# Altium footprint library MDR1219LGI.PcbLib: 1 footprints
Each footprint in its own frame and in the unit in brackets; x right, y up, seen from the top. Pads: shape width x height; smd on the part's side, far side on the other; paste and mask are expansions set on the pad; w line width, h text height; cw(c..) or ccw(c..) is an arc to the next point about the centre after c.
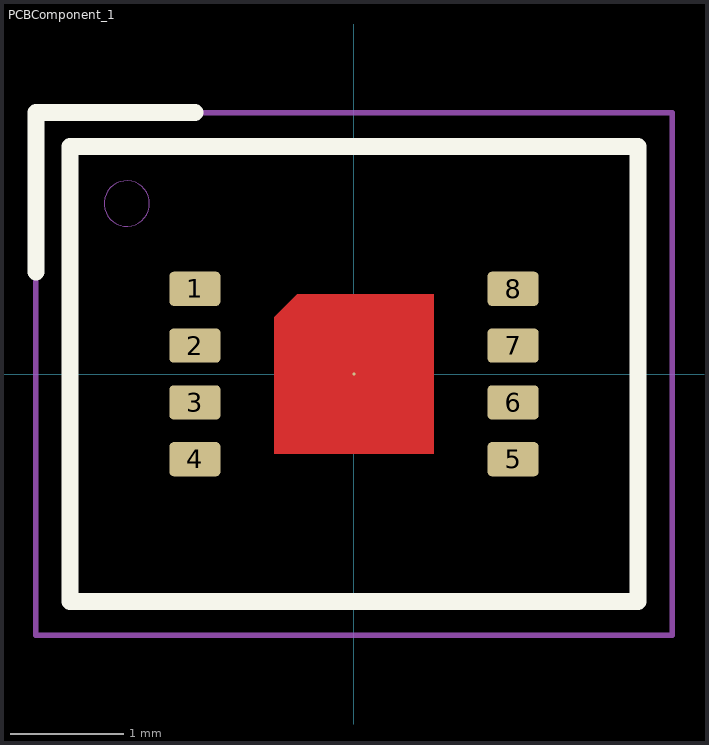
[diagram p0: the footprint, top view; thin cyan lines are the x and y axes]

## PCBComponent_1 [mm]
pads (9):
  rrect25% 0.45x0.3 smd mask+0.05: 1(-1.4,0.75) 2(-1.4,0.25) 3(-1.4,-0.25) 4(-1.4,-0.75) 5(1.4,-0.75) 6(1.4,-0.25) 7(1.4,0.25) 8(1.4,0.75)
  round 0.025 smd paste-2539.97 mask+0.05: 9(0,0)
Top Layer:
  region: -0.7,-0.7 0.7,-0.7 0.7,0.7 -0.5,0.7 -0.7,0.5
Top Overlay:
  lines w0.15: -2.8,0.9 -2.8,2.3 -1.4,2.3 ; -2.5,-2 -2.5,2 2.5,2 2.5,-2 -2.5,-2
Top Paste:
  drawing of 4 lines, arcs and shapes, not listed
Top Assembly:
  circle w0: c-2,1.5 r0.2
  lines w0: -2.5,-2 2.5,-2 2.5,2 -2.5,2 -2.5,-2
  text ".Designator" at -2.618,-0.355 h1.52
Top Courtyard:
  lines w0.05: -2.8,-2.3 -2.8,2.3 2.8,2.3 2.8,-2.3 -2.8,-2.3
3D body "LGA8 4x5x1,6 (0,5).STEP": height 1.6, standoff 0, extent -2.5,-2 2.5,2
